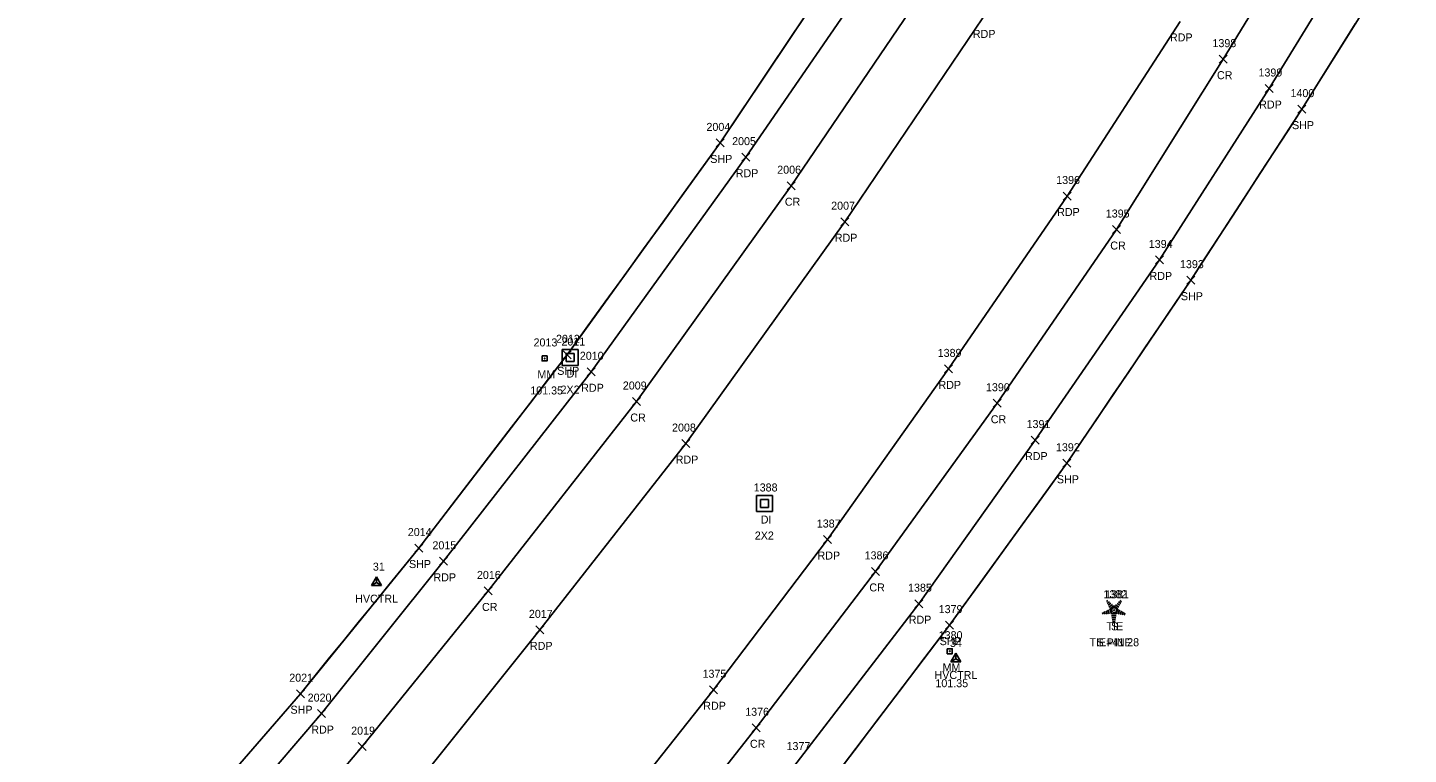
# Model space of a CAD drawing. Extents: x 1472022 to 1479249, y 777216 to 786527.
# Drawn here: x 1473041.7 to 1473386.7, y 778250.4 to 778431.9 of the extents above; entities that cross this region are included whole.
import ezdxf

# ---------------------------------------------------------------- set-up
doc = ezdxf.new("R2010")
doc.units = 0
for name, color, linetype in [('C_A', 7, 'Continuous'), ('C_C', 7, 'Continuous'), ('C_I', 7, 'Continuous'), ('CBP', 7, 'Continuous'), ('CPSM', 7, 'Continuous'), ('D_A', 7, 'Continuous'), ('D_C', 7, 'Continuous'), ('D_I', 7, 'Continuous'), ('DS', 7, 'Continuous'), ('L_A', 7, 'Continuous'), ('L_C', 7, 'Continuous'), ('L_I', 7, 'Continuous'), ('LSOGP', 7, 'Continuous'), ('LTC', 7, 'Continuous'), ('P_A', 7, 'Continuous'), ('P_I', 7, 'Continuous'), ('P_TIC', 7, 'Continuous'), ('PET', 7, 'Continuous'), ('PRC', 7, 'Continuous'), ('PSP', 7, 'Continuous'), ('S_A', 7, 'Continuous'), ('S_C', 7, 'Continuous'), ('S_I', 7, 'Continuous'), ('SRM', 7, 'Continuous')]:
    doc.layers.add(name, color=color, linetype=linetype)

msp = doc.modelspace()

# ---------------------------------------------------------------- linework, layer by layer
at = {"layer": 'CBP'}
for radius in [0.625, 0.0833]:
    msp.add_circle((1473313.2, 778286.42), radius, dxfattribs=at)
at = {"layer": 'CPSM'}
for p, q in [((1473127.6, 778292.58), (1473128.85, 778294.75)), ((1473127.6, 778292.58), (1473128.85, 778293.3)), ((1473127.6, 778292.58), (1473130.1, 778292.58)), ((1473130.1, 778292.58), (1473128.85, 778294.75)), ((1473128.85, 778293.3), (1473128.85, 778294.75)), ((1473128.85, 778293.3), (1473128.85, 778293.3)), ((1473128.85, 778293.3), (1473130.1, 778292.58)), ((1473272.36, 778273.52), (1473273.61, 778275.68)), ((1473274.86, 778273.52), (1473273.61, 778275.68)), ((1473273.61, 778274.24), (1473273.61, 778275.68)), ((1473272.36, 778273.52), (1473273.61, 778274.24)), ((1473272.36, 778273.52), (1473274.86, 778273.52)), ((1473273.61, 778274.24), (1473273.61, 778274.24)), ((1473273.61, 778274.24), (1473274.86, 778273.52))]:
    msp.add_line(p, q, dxfattribs=at)
at = {"layer": 'DS'}
for p, q in [((1473175.27, 778351.52), (1473179.27, 778351.52)), ((1473175.27, 778347.52), (1473175.27, 778351.52)), ((1473179.27, 778351.52), (1473179.27, 778347.52)), ((1473179.27, 778347.52), (1473175.27, 778347.52)), ((1473176.27, 778348.52), (1473176.27, 778350.52)), ((1473176.27, 778350.52), (1473178.27, 778350.52)), ((1473178.27, 778348.52), (1473176.27, 778348.52)), ((1473177.28, 778349.52), (1473177.28, 778349.52)), ((1473177.28, 778349.52), (1473177.28, 778349.52)), ((1473178.27, 778350.52), (1473178.27, 778348.52)), ((1473223.81, 778315.07), (1473227.81, 778315.07)), ((1473223.81, 778311.07), (1473223.81, 778315.07)), ((1473224.81, 778312.07), (1473224.81, 778314.07)), ((1473224.81, 778314.07), (1473226.81, 778314.07)), ((1473225.81, 778313.07), (1473225.81, 778313.07)), ((1473225.81, 778313.07), (1473225.81, 778313.07)), ((1473226.81, 778314.07), (1473226.81, 778312.07)), ((1473227.81, 778315.07), (1473227.81, 778311.07)), ((1473227.81, 778311.07), (1473223.81, 778311.07)), ((1473226.81, 778312.07), (1473224.81, 778312.07))]:
    msp.add_line(p, q, dxfattribs=at)
at = {"layer": 'LSOGP'}
for points in [[(1473235.77, 778434.59), (1473231.56, 778428.3), (1473227.35, 778422), (1473223.14, 778415.71), (1473218.93, 778409.42), (1473214.72, 778403.13), (1473209.94, 778396.51), (1473205.16, 778389.9), (1473200.38, 778383.28), (1473195.6, 778376.66), (1473190.82, 778370.05), (1473186.04, 778363.43), (1473181.26, 778356.82), (1473176.48, 778350.2), (1473171.85, 778344.17), (1473167.22, 778338.14), (1473162.59, 778332.1), (1473157.96, 778326.07), (1473153.34, 778320.04), (1473148.71, 778314), (1473144.08, 778307.97), (1473139.45, 778301.94), (1473135.75, 778297.39), (1473132.04, 778292.84), (1473128.34, 778288.3), (1473124.64, 778283.75), (1473120.94, 778279.2), (1473117.24, 778274.65), (1473113.53, 778270.11), (1473109.83, 778265.56), (1473105.51, 778260.56), (1473101.19, 778255.56), (1473096.87, 778250.57), (1473092.55, 778245.57)], [(1473245.79, 778248.15), (1473249.54, 778253.08), (1473253.29, 778258.02), (1473257.04, 778262.95), (1473260.79, 778267.88), (1473264.54, 778272.82), (1473268.29, 778277.75), (1473272.04, 778282.69), (1473275.7, 778287.74), (1473279.37, 778292.79), (1473283.03, 778297.85), (1473286.69, 778302.9), (1473290.35, 778307.95), (1473294.01, 778313.01), (1473297.67, 778318.06), (1473301.33, 778323.12), (1473305.21, 778328.83), (1473309.08, 778334.55), (1473312.96, 778340.27), (1473316.83, 778345.98), (1473320.7, 778351.7), (1473324.58, 778357.42), (1473328.45, 778363.14), (1473332.33, 778368.85), (1473335.8, 778374.19), (1473339.27, 778379.53), (1473342.74, 778384.87), (1473346.22, 778390.21), (1473349.69, 778395.55), (1473353.16, 778400.89), (1473356.63, 778406.23), (1473360.11, 778411.57), (1473363.43, 778416.89), (1473366.76, 778422.21), (1473370.08, 778427.53), (1473373.41, 778432.85)]]:
    msp.add_lwpolyline(points, dxfattribs=at)
at = {"layer": 'LTC'}
for p, q in [((1473310.27, 778285.86), (1473310.43, 778285.4)), ((1473310.73, 778286.08), (1473310.94, 778285.43)), ((1473311.18, 778286.3), (1473311.46, 778285.46)), ((1473311.24, 778288.59), (1473311.6, 778288.84)), ((1473311.45, 778288.12), (1473311.98, 778288.5)), ((1473311.64, 778286.51), (1473311.97, 778285.5)), ((1473311.66, 778287.65), (1473312.36, 778288.17)), ((1473311.87, 778287.19), (1473312.75, 778287.83)), ((1473312.09, 778286.73), (1473313.11, 778287.47)), ((1473312.09, 778286.73), (1473312.48, 778285.54)), ((1473313.71, 778285.54), (1473312.48, 778285.54)), ((1473313.11, 778287.47), (1473314.1, 778286.74)), ((1473313.53, 778287.78), (1473314.34, 778287.19)), ((1473314.1, 778286.74), (1473313.71, 778285.54)), ((1473313.9, 778288.13), (1473314.58, 778287.64)), ((1473314.54, 778286.47), (1473314.2, 778285.43)), ((1473314.27, 778288.48), (1473314.82, 778288.08)), ((1473314.64, 778288.83), (1473315.06, 778288.52)), ((1473314.98, 778286.22), (1473314.7, 778285.34)), ((1473315.43, 778285.97), (1473315.19, 778285.24)), ((1473315.87, 778285.72), (1473315.69, 778285.15)), ((1473313.67, 778285.04), (1473312.53, 778285.04)), ((1473313.59, 778284.54), (1473312.6, 778284.54)), ((1473313.51, 778284.04), (1473312.67, 778284.04)), ((1473313.42, 778283.54), (1473312.75, 778283.54))]:
    msp.add_line(p, q, dxfattribs=at)
at = {"layer": 'P_TIC'}
for points in [[(1473339.44, 778423.05), (1473341.44, 778425.05)], [(1473341.44, 778423.05), (1473339.44, 778425.05)], [(1473350.95, 778415.72), (1473352.95, 778417.72)], [(1473352.95, 778415.72), (1473350.95, 778417.72)], [(1473359.11, 778410.57), (1473361.11, 778412.57)], [(1473361.11, 778410.57), (1473359.11, 778412.57)], [(1473213.72, 778402.13), (1473215.72, 778404.13)], [(1473215.72, 778402.13), (1473213.72, 778404.13)], [(1473220.14, 778398.57), (1473222.14, 778400.57)], [(1473222.14, 778398.57), (1473220.14, 778400.57)], [(1473231.46, 778391.44), (1473233.46, 778393.44)], [(1473233.46, 778391.44), (1473231.46, 778393.44)], [(1473300.45, 778388.87), (1473302.45, 778390.87)], [(1473302.45, 778388.87), (1473300.45, 778390.87)], [(1473244.89, 778382.45), (1473246.89, 778384.45)], [(1473246.89, 778382.45), (1473244.89, 778384.45)], [(1473312.78, 778380.5), (1473314.78, 778382.5)], [(1473314.78, 778380.5), (1473312.78, 778382.5)], [(1473323.53, 778372.9), (1473325.53, 778374.9)], [(1473325.53, 778372.9), (1473323.53, 778374.9)], [(1473331.33, 778367.85), (1473333.33, 778369.85)], [(1473333.33, 778367.85), (1473331.33, 778369.85)], [(1473175.48, 778349.2), (1473177.48, 778351.2)], [(1473177.48, 778349.2), (1473175.48, 778351.2)], [(1473270.79, 778345.69), (1473272.79, 778347.69)], [(1473272.79, 778345.69), (1473270.79, 778347.69)], [(1473181.52, 778344.97), (1473183.52, 778346.97)], [(1473183.52, 778344.97), (1473181.52, 778346.97)], [(1473192.83, 778337.54), (1473194.83, 778339.54)], [(1473194.83, 778337.54), (1473192.83, 778339.54)], [(1473282.93, 778337.11), (1473284.93, 778339.11)], [(1473284.93, 778337.11), (1473282.93, 778339.11)], [(1473205.13, 778327.04), (1473207.13, 778329.04)], [(1473207.13, 778327.04), (1473205.13, 778329.04)], [(1473292.42, 778327.91), (1473294.42, 778329.91)], [(1473294.42, 778327.91), (1473292.42, 778329.91)], [(1473300.33, 778322.12), (1473302.33, 778324.12)], [(1473302.33, 778322.12), (1473300.33, 778324.12)], [(1473138.45, 778300.94), (1473140.45, 778302.94)], [(1473140.45, 778300.94), (1473138.45, 778302.94)], [(1473240.58, 778303.07), (1473242.58, 778305.07)], [(1473242.58, 778303.07), (1473240.58, 778305.07)], [(1473144.62, 778297.63), (1473146.62, 778299.63)], [(1473146.62, 778297.63), (1473144.62, 778299.63)], [(1473252.58, 778295.11), (1473254.58, 778297.11)], [(1473254.58, 778295.11), (1473252.58, 778297.11)], [(1473155.79, 778290.23), (1473157.79, 778292.23)], [(1473157.79, 778290.23), (1473155.79, 778292.23)], [(1473263.38, 778287.05), (1473265.38, 778289.05)], [(1473265.38, 778287.05), (1473263.38, 778289.05)], [(1473168.71, 778280.51), (1473170.71, 778282.51)], [(1473170.71, 778280.51), (1473168.71, 778282.51)], [(1473271.04, 778281.69), (1473273.04, 778283.69)], [(1473273.04, 778281.69), (1473271.04, 778283.69)], [(1473108.83, 778264.56), (1473110.83, 778266.56)], [(1473110.83, 778264.56), (1473108.83, 778266.56)], [(1473212.03, 778265.55), (1473214.03, 778267.55)], [(1473214.03, 778265.55), (1473212.03, 778267.55)], [(1473114.08, 778259.59), (1473116.08, 778261.59)], [(1473116.08, 778259.59), (1473114.08, 778261.59)], [(1473222.74, 778256.05), (1473224.74, 778258.05)], [(1473224.74, 778256.05), (1473222.74, 778258.05)], [(1473124.31, 778251.34), (1473126.31, 778253.34)], [(1473126.31, 778251.34), (1473124.31, 778253.34)]]:
    msp.add_lwpolyline(points, dxfattribs=at)
at = {"layer": 'PET'}
for points in [[(1472671.07, 777717.85), (1472704.16, 777745.65), (1472742.8, 777777.83), (1472783.82, 777812.54), (1472835.62, 777856.03), (1472877.54, 777891.75), (1472912.91, 777921.62), (1472958.15, 777961.39), (1472998.19, 777996.96), (1473034.38, 778029.89), (1473069.02, 778063.25), (1473104.62, 778099.15), (1473138.55, 778134.62), (1473170.95, 778171.61), (1473202.72, 778209.33), (1473234.01, 778248.48), (1473264.38, 778288.05), (1473293.42, 778328.91), (1473324.53, 778373.9), (1473351.95, 778416.72), (1473378.27, 778459.7)], [(1473255.52, 778449.63), (1473221.14, 778399.57), (1473182.52, 778345.97), (1473145.62, 778298.63), (1473115.08, 778260.59), (1473080.6, 778220.31), (1473051.25, 778186.84), (1473016.92, 778151.59), (1472979.91, 778114.91), (1472945.26, 778082.84), (1472907.77, 778049.38), (1472868.55, 778015.69), (1472837.98, 777989.81), (1472804.85, 777962.23), (1472766.82, 777929.84), (1472722.68, 777892.48), (1472682.88, 777859.11)], [(1473280.39, 778434.36), (1473245.89, 778383.45), (1473206.13, 778328.04), (1473169.71, 778281.51), (1473137.09, 778240.78), (1473104.04, 778201.77), (1473072.67, 778166.5), (1473037.86, 778129.91), (1472999.85, 778092.99), (1472964.39, 778060.83), (1472926.51, 778026.82), (1472887.44, 777993.06), (1472857.66, 777967.76), (1472824.92, 777940.5), (1472785.25, 777907.17), (1472741.34, 777869.88), (1472700.25, 777835.4), (1472658.9, 777800.89)], [(1472684.83, 777767.44), (1472722.55, 777799.22), (1472766.23, 777836.23), (1472817.16, 777878.96), (1472857.89, 777913.52), (1472893.26, 777943.27), (1472939.5, 777982.83), (1472979.03, 778017.29), (1473015.7, 778051.25), (1473048.8, 778083.05), (1473084.2, 778118.03), (1473117.72, 778153.52), (1473150.86, 778190.79), (1473181.06, 778226.14), (1473213.03, 778266.55), (1473241.58, 778304.07), (1473271.79, 778346.69), (1473301.45, 778389.87), (1473329.64, 778433.49)]]:
    msp.add_lwpolyline(points, dxfattribs=at)
at = {"layer": 'PRC'}
for points in [[(1472662.17, 777728.39), (1472695.49, 777755.92), (1472733.11, 777787.35), (1472775.04, 777822.62), (1472827.37, 777866.4), (1472869.28, 777902.04), (1472903.96, 777930.47), (1472949.73, 777971.08), (1472949.47, 777970.99), (1472989.06, 778006.22), (1473025.25, 778040), (1473059.42, 778072.88), (1473096.86, 778110.7), (1473128.36, 778143.66), (1473160.84, 778180.37), (1473192.67, 778217.6), (1473223.74, 778257.05), (1473253.58, 778296.11), (1473283.93, 778338.11), (1473313.78, 778381.5), (1473340.44, 778424.05), (1473366.77, 778467.15)], [(1473266.55, 778442.63), (1473232.46, 778392.44), (1473193.83, 778338.54), (1473156.79, 778291.23), (1473125.31, 778252.34), (1473091.58, 778212.42), (1473060.19, 778177.45), (1473026.49, 778141.75), (1472989.07, 778105.13), (1472954.29, 778073.26), (1472916.06, 778039.37), (1472877.51, 778005.85), (1472846.53, 777979.57), (1472813.91, 777952.49), (1472775.15, 777919.54), (1472731.22, 777882.43), (1472690.51, 777848.29)]]:
    msp.add_lwpolyline(points, dxfattribs=at)
at = {"layer": 'PSP'}
for points in [[(1473248.4, 778453.47), (1473214.72, 778403.13), (1473176.48, 778350.2), (1473139.45, 778301.94), (1473109.83, 778265.56), (1473075.26, 778225.58), (1473045.72, 778192.54), (1473029.49, 778175.6), (1473012.03, 778157.81), (1472973.92, 778120.85), (1472936.46, 778086.53), (1472902.36, 778055.99), (1472863.3, 778022.57), (1472832.68, 777997.03), (1472798.65, 777968.31), (1472761.65, 777936.81), (1472716.04, 777898.78), (1472676.55, 777865.69)], [(1472676.6, 777710.94), (1472709.07, 777738.21), (1472747.84, 777770.74), (1472788.89, 777806.21), (1472798.61, 777813.61), (1472840.19, 777850.33), (1472882.46, 777885.36), (1472918.99, 777916.31), (1472964.12, 777954.9), (1473004.91, 777990.69), (1473041.16, 778023.65), (1473075.83, 778056.69), (1473111.08, 778092.16), (1473145.38, 778128.69), (1473178.22, 778165.74), (1473210.98, 778203.71), (1473242.04, 778243.22), (1473272.04, 778282.69), (1473301.33, 778323.12), (1473332.33, 778368.85), (1473360.11, 778411.57), (1473386.71, 778454.12)]]:
    msp.add_lwpolyline(points, dxfattribs=at)
at = {"layer": 'SRM'}
for points in [[(1473170.24, 778349.93), (1473171.49, 778349.93), (1473171.49, 778348.68), (1473170.24, 778348.68)], [(1473271.49, 778276.81), (1473272.74, 778276.81), (1473272.74, 778275.56), (1473271.49, 778275.56)]]:
    msp.add_lwpolyline(points, close=True, dxfattribs=at)
for centre in [(1473170.87, 778349.3), (1473272.12, 778276.18)]:
    msp.add_circle(centre, 0.0833, dxfattribs=at)

# ---------------------------------------------------------------- texts
at = {"layer": 'C_A'}
for s, p in [('HVCTRL', (1473123.54, 778288.3)), ('TIE', (1473311.28, 778281.42)), ('HVCTRL', (1473268.3, 778269.24))]:
    msp.add_text(s, height=2, dxfattribs=at).set_placement(p)
at = {"layer": 'C_C'}
msp.add_text('TIE=41.28', height=2, dxfattribs=at).set_placement((1473307, 778277.42))
at = {"layer": 'C_I'}
for s, p in [('31', (1473127.95, 778296.3)), ('1382', (1473310.51, 778289.42)), ('34', (1473272.15, 778277.24))]:
    msp.add_text(s, height=2, dxfattribs=at).set_placement(p)
at = {"layer": 'D_A'}
for p in [(1473176.33, 778344.52), (1473224.87, 778308.07)]:
    msp.add_text('DI', height=2, dxfattribs=at).set_placement(p)
at = {"layer": 'D_C'}
for p in [(1473174.85, 778340.52), (1473223.39, 778304.07)]:
    msp.add_text('2X2', height=2, dxfattribs=at).set_placement(p)
at = {"layer": 'D_I'}
for s, p in [('2011', (1473175.07, 778352.52)), ('1388', (1473223.12, 778316.07))]:
    msp.add_text(s, height=2, dxfattribs=at).set_placement(p)
at = {"layer": 'L_A'}
msp.add_text('S', height=2, dxfattribs=at).set_placement((1473312.43, 778281.38))
at = {"layer": 'L_C'}
msp.add_text('S.PINE', height=2, dxfattribs=at).set_placement((1473308.78, 778277.38))
at = {"layer": 'L_I'}
msp.add_text('1381', height=2, dxfattribs=at).set_placement((1473310.92, 778289.38))
at = {"layer": 'LTC'}
msp.add_text('.', height=1.04, rotation=270, dxfattribs=at).set_placement((1473312.99, 778286.48))
at = {"layer": 'P_A'}
for s, p in [('RDP', (1473277.88, 778429.36)), ('RDP', (1473327.13, 778428.49)), ('CR', (1473338.87, 778419.05)), ('RDP', (1473349.43, 778411.72)), ('SHP', (1473357.64, 778406.57)), ('SHP', (1473212.26, 778398.13)), ('RDP', (1473218.62, 778394.57)), ('CR', (1473230.9, 778387.44)), ('RDP', (1473298.94, 778384.87)), ('RDP', (1473243.38, 778378.45)), ('CR', (1473312.21, 778376.5)), ('RDP', (1473322.02, 778368.9)), ('SHP', (1473329.86, 778363.85)), ('SHP', (1473174.02, 778345.2)), ('RDP', (1473180.01, 778340.97)), ('RDP', (1473269.28, 778341.69)), ('CR', (1473192.27, 778333.54)), ('CR', (1473282.36, 778333.11)), ('RDP', (1473203.62, 778323.04)), ('RDP', (1473290.91, 778323.91)), ('SHP', (1473298.87, 778318.12)), ('RDP', (1473239.06, 778299.07)), ('SHP', (1473136.98, 778296.94)), ('RDP', (1473143.1, 778293.63)), ('CR', (1473252.01, 778291.11)), ('CR', (1473155.22, 778286.23)), ('RDP', (1473261.86, 778283.05)), ('SHP', (1473269.58, 778277.69)), ('RDP', (1473167.2, 778276.51)), ('SHP', (1473107.37, 778260.56)), ('RDP', (1473210.51, 778261.55)), ('RDP', (1473112.57, 778255.59)), ('CR', (1473222.17, 778252.05))]:
    msp.add_text(s, height=2, dxfattribs=at).set_placement(p)
at = {"layer": 'P_I'}
for s, p in [('1398', (1473337.75, 778427.05)), ('1399', (1473349.25, 778419.72)), ('1400', (1473357.25, 778414.57)), ('2004', (1473211.31, 778406.13)), ('2005', (1473217.72, 778402.57)), ('2006', (1473228.99, 778395.44)), ('1396', (1473298.7, 778392.87)), ('2007', (1473242.47, 778386.45)), ('1395', (1473311.09, 778384.5)), ('1394', (1473321.84, 778376.9)), ('1393', (1473329.63, 778371.85)), ('2012', (1473173.71, 778353.2)), ('2010', (1473179.67, 778348.97)), ('1389', (1473269.09, 778349.69)), ('2009', (1473190.41, 778341.54)), ('1390', (1473281.15, 778341.11)), ('1391', (1473291.3, 778331.91)), ('2008', (1473202.71, 778331.04)), ('1392', (1473298.64, 778326.12)), ('2014', (1473136.68, 778304.94)), ('1387', (1473238.88, 778307.07)), ('2015', (1473142.84, 778301.63)), ('1386', (1473250.83, 778299.11)), ('2016', (1473153.96, 778294.23)), ('1385', (1473261.68, 778291.05)), ('2017', (1473166.94, 778284.51)), ('1379', (1473269.34, 778285.69)), ('2021', (1473107.06, 778268.56)), ('1375', (1473210.33, 778269.55)), ('2020', (1473111.66, 778263.59)), ('1376', (1473220.99, 778260.05)), ('2019', (1473122.53, 778255.34)), ('1377', (1473231.32, 778251.48))]:
    msp.add_text(s, height=2, dxfattribs=at).set_placement(p)
at = {"layer": 'S_A'}
for p in [(1473169.06, 778344.3), (1473270.3, 778271.18)]:
    msp.add_text('MM', height=2, dxfattribs=at).set_placement(p)
at = {"layer": 'S_C'}
for p in [(1473167.28, 778340.3), (1473268.52, 778267.18)]:
    msp.add_text('101.35', height=2, dxfattribs=at).set_placement(p)
at = {"layer": 'S_I'}
for s, p in [('2013', (1473168.1, 778352.3)), ('1380', (1473269.34, 778279.18))]:
    msp.add_text(s, height=2, dxfattribs=at).set_placement(p)

doc.saveas('drawing.dxf')
